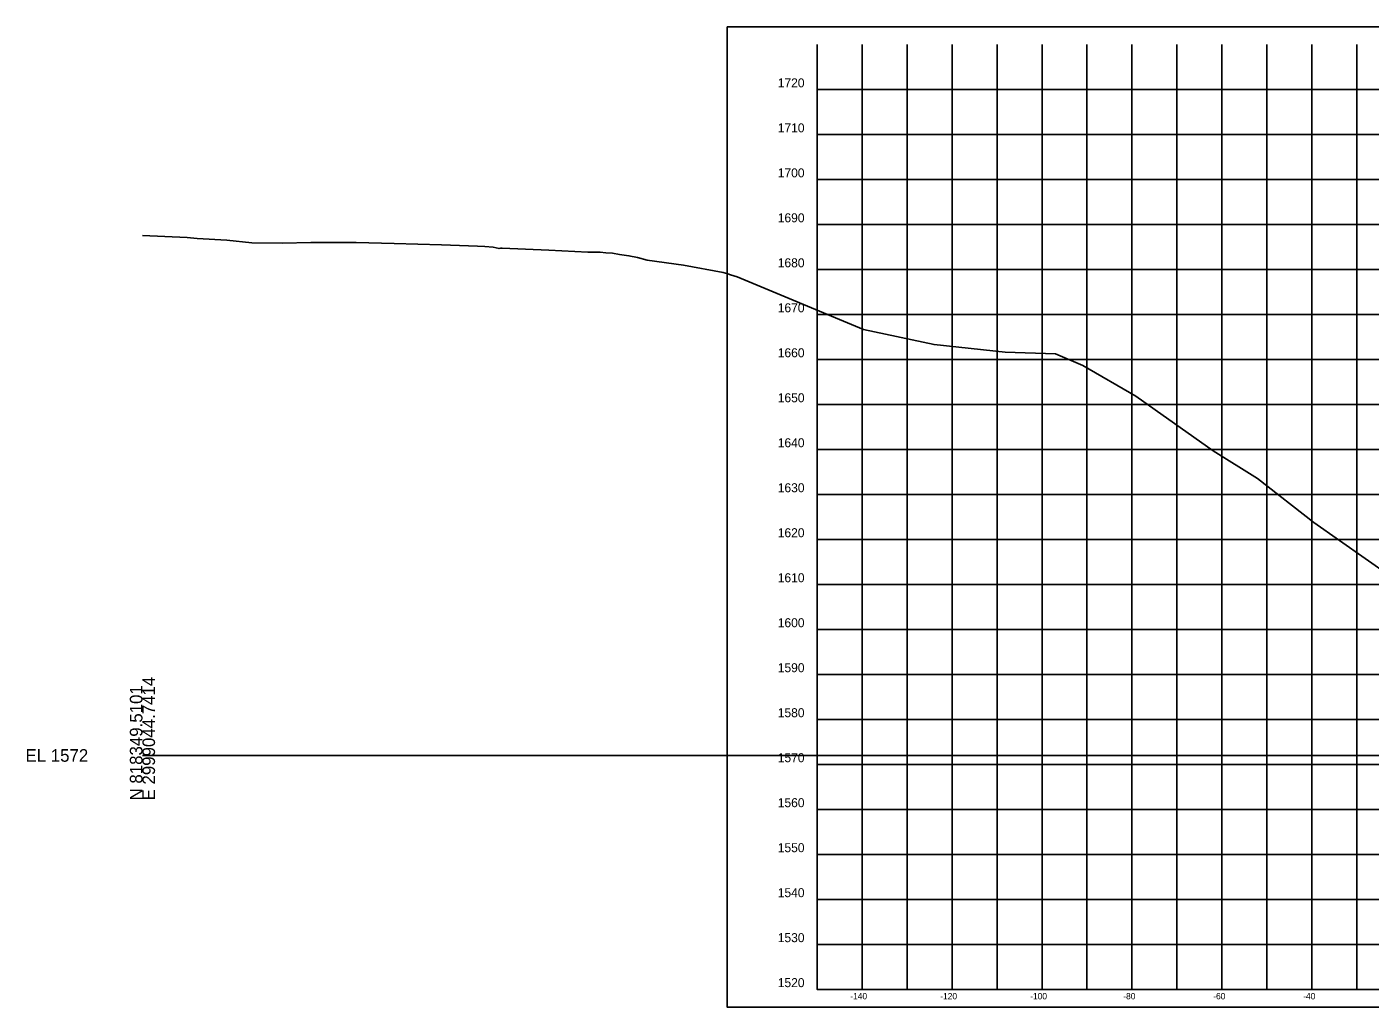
# Model space of a CAD drawing. Extents: x -26 to 1067, y -71 to 1837.
# Drawn here: x -25.7 to 272.9, y 944.1 to 1161.9 of the extents above; entities that cross this region are included whole.
import ezdxf

# ---------------------------------------------------------------- set-up
doc = ezdxf.new("R2010")
doc.units = 0
for name, color, linetype in [('DESIGN - SHEET - Corner Text', 7, 'Continuous'), ('DESIGN - SHEET - Light Grid', 7, 'Continuous'), ('DESIGN - SHEET - Linework', 7, 'Continuous'), ('DESIGN - SHEET - Plot Shape', 7, 'Continuous'), ('SURVEY - GROUND - Top of Ground', 7, 'Continuous')]:
    doc.layers.add(name, color=color, linetype=linetype)

msp = doc.modelspace()

# ---------------------------------------------------------------- linework, layer by layer
at = {"layer": 'DESIGN - SHEET - Light Grid'}
msp.add_line((0, 1000), (300, 1000), dxfattribs=at)
at = {"layer": 'DESIGN - SHEET - Linework'}
for p, q in [((160, 948), (160, 1158)), ((170, 948), (170, 1158)), ((180, 948), (180, 1158)), ((190, 948), (190, 1158)), ((200, 948), (200, 1158)), ((210, 948), (210, 1158)), ((220, 948), (220, 1158)), ((230, 948), (230, 1158)), ((240, 948), (240, 1158)), ((250, 948), (250, 1158)), ((260, 948), (260, 1158)), ((270, 948), (270, 1158)), ((150, 1148), (450, 1148)), ((150, 1138), (450, 1138)), ((150, 1128), (450, 1128)), ((150, 1118), (450, 1118)), ((150, 1108), (450, 1108)), ((150, 1098), (450, 1098)), ((150, 1088), (450, 1088)), ((150, 1078), (450, 1078)), ((150, 1068), (450, 1068)), ((150, 1058), (450, 1058)), ((150, 1048), (450, 1048)), ((150, 1038), (450, 1038)), ((150, 1028), (450, 1028)), ((150, 1018), (450, 1018)), ((150, 1008), (450, 1008)), ((150, 998), (450, 998)), ((150, 988), (450, 988)), ((150, 978), (450, 978)), ((150, 968), (450, 968)), ((150, 958), (450, 958))]:
    msp.add_line(p, q, dxfattribs=at)
msp.add_lwpolyline([(150, 1158), (150, 948), (450, 948), (450, 1158)], dxfattribs=at)
at = {"layer": 'DESIGN - SHEET - Plot Shape'}
msp.add_lwpolyline([(130, 1161.94), (470, 1161.94), (470, 944.06), (130, 944.06)], close=True, dxfattribs=at)
at = {"layer": 'SURVEY - GROUND - Top of Ground'}
msp.add_lwpolyline([(0, 1115.57), (9.92, 1115.09), (12.2, 1114.91), (18.77, 1114.56), (24.29, 1113.97), (31.15, 1113.9), (37.43, 1113.98), (47.51, 1114.02), (55.94, 1113.76), (66.51, 1113.52), (74.47, 1113.2), (76.13, 1113.12), (77.95, 1112.95), (79.3, 1112.65), (79.61, 1112.72), (79.95, 1112.72), (90.35, 1112.29), (99, 1111.9), (101.21, 1111.84), (101.78, 1111.85), (103.04, 1111.71), (104.48, 1111.61), (106.03, 1111.36), (108.17, 1111.05), (110.1, 1110.65), (112.18, 1110.1), (120.28, 1108.98), (129.09, 1107.32), (130.13, 1107.08), (130.74, 1106.85), (132.23, 1106.37), (160.3, 1094.66), (176.01, 1091.32), (191.81, 1089.64), (203.02, 1089.3), (209.06, 1086.69), (220.87, 1079.84), (238.07, 1067.7), (247.88, 1061.53), (260.45, 1051.8), (277.55, 1039.78)], dxfattribs=at)

# ---------------------------------------------------------------- texts
at = {"layer": 'DESIGN - SHEET - Corner Text'}
for s, height, p in [('1720', 2, (141.25, 1148.5)), ('1710', 2, (141.25, 1138.5)), ('1700', 2, (141.25, 1128.5)), ('1690', 2, (141.25, 1118.5)), ('1680', 2, (141.25, 1108.5)), ('1670', 2, (141.25, 1098.5)), ('1660', 2, (141.25, 1088.5)), ('1650', 2, (141.25, 1078.5)), ('1640', 2, (141.25, 1068.5)), ('1630', 2, (141.25, 1058.5)), ('1620', 2, (141.25, 1048.5)), ('1610', 2, (141.25, 1038.5)), ('1600', 2, (141.25, 1028.5)), ('1590', 2, (141.25, 1018.5)), ('1580', 2, (141.25, 1008.5)), ('1570', 2, (141.25, 998.5)), ('1560', 2, (141.25, 988.5)), ('1550', 2, (141.25, 978.5)), ('1540', 2, (141.25, 968.5)), ('1530', 2, (141.25, 958.5)), ('1520', 2, (141.25, 948.5)), ('-140', 1.4, (157.37, 945.8)), ('-120', 1.4, (177.37, 945.8)), ('-100', 1.4, (197.37, 945.8)), ('-80', 1.4, (218.06, 945.8)), ('-60', 1.4, (238.06, 945.8)), ('-40', 1.4, (258.06, 945.8))]:
    msp.add_text(s, height=height, dxfattribs=at).set_placement(p)
at = {"layer": 'DESIGN - SHEET - Light Grid'}
for s, p in [('N 818349.5101', (0, 990)), ('E 2999044.7414', (2.8, 990))]:
    msp.add_text(s, height=2.8, rotation=90, dxfattribs=at).set_placement(p)
msp.add_text('EL 1572', height=2.8, dxfattribs=at).set_placement((-26, 998.6))

doc.saveas('drawing.dxf')
